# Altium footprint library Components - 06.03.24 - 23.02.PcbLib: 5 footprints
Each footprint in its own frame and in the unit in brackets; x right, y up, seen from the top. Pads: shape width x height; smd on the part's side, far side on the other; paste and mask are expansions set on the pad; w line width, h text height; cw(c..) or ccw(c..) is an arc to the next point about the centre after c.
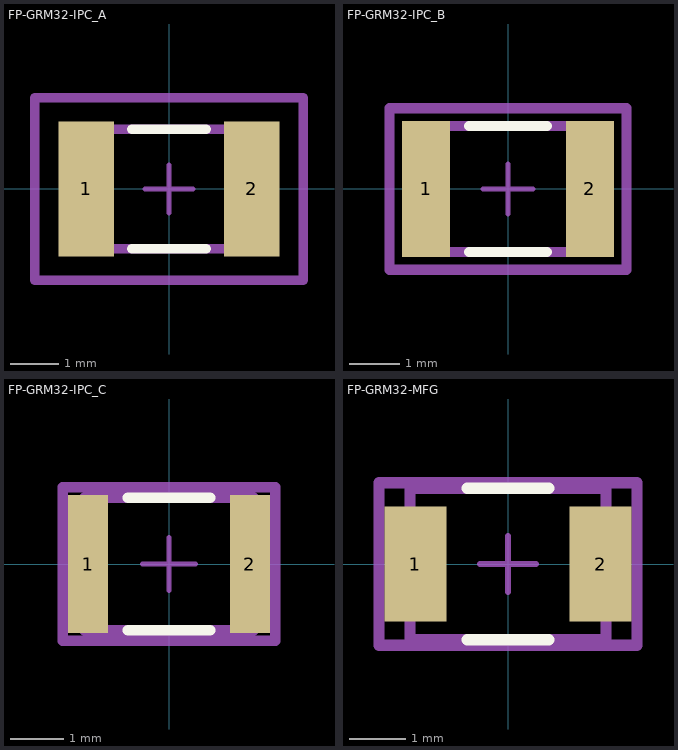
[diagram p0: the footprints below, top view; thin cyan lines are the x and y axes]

## FP-GRM32-IPC_A [mm]
pads (2):
  rect 1.154x2.806 smd paste+0 mask+0: 1(-1.725,0) 2(1.725,0)
Top Overlay:
  lines w0.2: -0.773,-1.25 0.773,-1.25 ; -0.773,1.25 0.773,1.25
Mechanical 5:
  lines w0.2: -2.802,-1.903 2.802,-1.903 2.802,1.903 -2.802,1.903 -2.802,-1.903
  text ".Designator" at 0,0.188 h1
Mechanical 13:
  lines w0.2: -1.6,-1.25 1.6,-1.25 1.6,1.25 -1.6,1.25 -1.6,-1.25
Mechanical 15:
  lines w0.2: -2.802,-1.903 2.802,-1.903 2.802,1.903 -2.802,1.903 -2.802,-1.903
Mechanical 16:
  lines w0.1: -0.5,0 0.5,0 ; 0,-0.5 0,0.5
3D body "Cap_Murata_GRM32ER71H106KA12L_eec.STEP": height 0.25, standoff 0, extent -2.802,-1.903 2.802,1.903

## FP-GRM32-IPC_B [mm]
pads (2):
  rect 0.954x2.706 smd paste+0 mask+0: 1(-1.625,0) 2(1.625,0)
Top Overlay:
  lines w0.2: -0.773,-1.25 0.773,-1.25 ; -0.773,1.25 0.773,1.25
Mechanical 5:
  lines w0.2: -2.352,-1.603 2.352,-1.603 2.352,1.603 -2.352,1.603 -2.352,-1.603
  text ".Designator" at 0,0.188 h1
Mechanical 13:
  lines w0.2: -1.6,-1.25 1.6,-1.25 1.6,1.25 -1.6,1.25 -1.6,-1.25
Mechanical 15:
  lines w0.2: -2.352,-1.603 2.352,-1.603 2.352,1.603 -2.352,1.603 -2.352,-1.603
Mechanical 16:
  lines w0.1: -0.5,0 0.5,0 ; 0,-0.5 0,0.5
3D body "Cap_Murata_GRM32ER71H106KA12L_eec.STEP": height 0.25, standoff 0, extent -2.352,-1.603 2.352,1.603

## FP-GRM32-IPC_C [mm]
pads (2):
  rect 0.754x2.606 smd paste+0 mask+0: 1(-1.525,0) 2(1.525,0)
Top Overlay:
  lines w0.2: -0.773,-1.25 0.773,-1.25 ; -0.773,1.25 0.773,1.25
Mechanical 5:
  lines w0.2: -2.002,-1.45 2.002,-1.45 2.002,1.45 -2.002,1.45 -2.002,-1.45
  text ".Designator" at 0,0.188 h1
Mechanical 13:
  lines w0.2: -1.6,-1.25 1.6,-1.25 1.6,1.25 -1.6,1.25 -1.6,-1.25
Mechanical 15:
  lines w0.2: -2.002,-1.45 2.002,-1.45 2.002,1.45 -2.002,1.45 -2.002,-1.45
Mechanical 16:
  lines w0.1: -0.5,0 0.5,0 ; 0,-0.5 0,0.5
3D body "Cap_Murata_GRM32ER71H106KA12L_eec.STEP": height 0.25, standoff 0, extent -2.002,-1.45 2.002,1.45

## FP-GRM32-MFG [mm]
pads (2):
  rect 1.1x2.05 smd paste+0 mask+0: 1(-1.65,0) 2(1.65,0)
Top Overlay:
  lines w0.2: -0.725,-1.35 0.725,-1.35 ; -0.725,1.35 0.725,1.35
Mechanical 5:
  lines w0.2: -2.3,-1.45 2.3,-1.45 2.3,1.45 -2.3,1.45 -2.3,-1.45
  text ".Designator" at 0,0.188 h1
Mechanical 13:
  lines w0.2: -1.75,-1.35 1.75,-1.35 1.75,1.35 -1.75,1.35 -1.75,-1.35
Mechanical 15:
  lines w0.2: -2.3,-1.45 2.3,-1.45 2.3,1.45 -2.3,1.45 -2.3,-1.45
Mechanical 16:
  lines w0.1: -0.5,0 0.5,0 ; 0,-0.5 0,0.5
3D body "Cap_Murata_GRM32ER71H106KA12L_eec.STEP": height 0.25, standoff 0, extent -2.3,-1.45 2.3,1.45

## PCBComponent_1 [mm]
